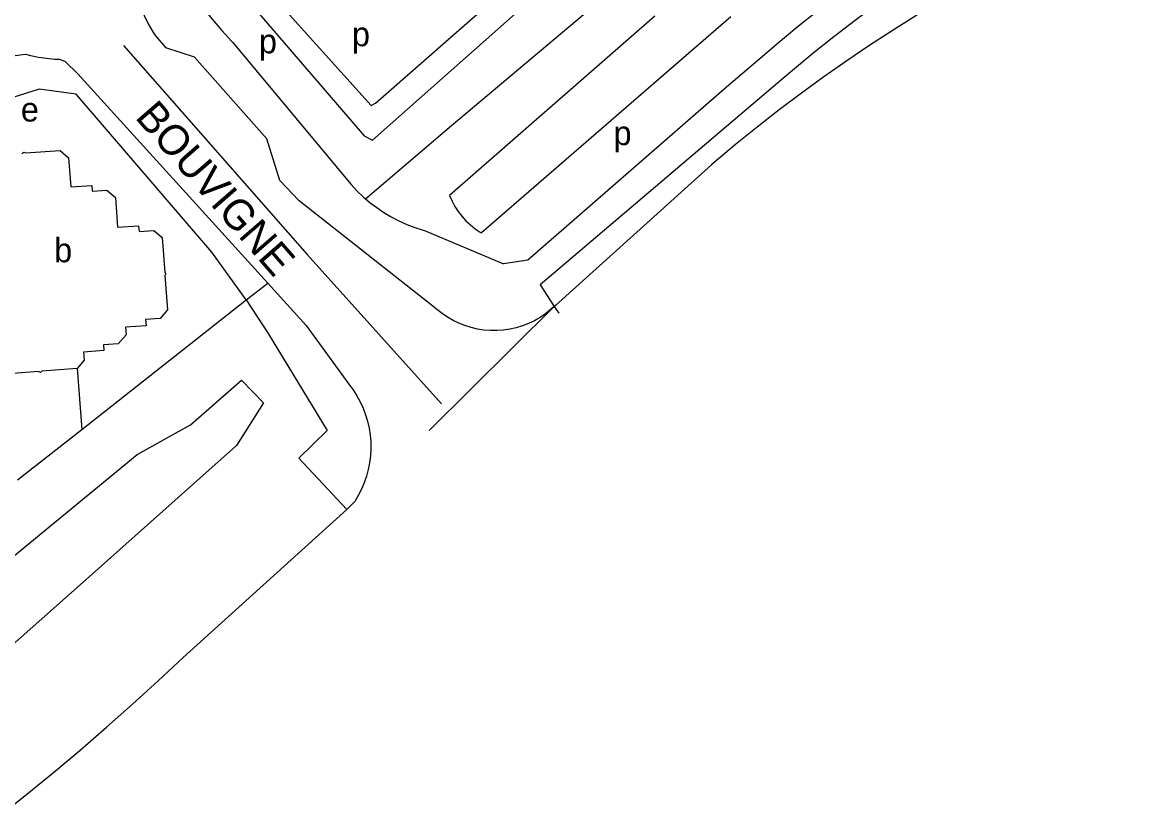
# Model space of a CAD drawing. Extents: x 157794 to 159375, y 380877 to 382306.
# Drawn here: x 158233.2 to 158416.4, y 380963.8 to 381095.2 of the extents above; entities that cross this region are included whole.
import ezdxf

# ---------------------------------------------------------------- set-up
doc = ezdxf.new("R2010")
doc.units = 0
for name, color, linetype in [('BLT_Basislijn', 7, 'Continuous'), ('BLT_Bebouwing', 7, 'Continuous'), ('BLT_Centroide', 7, 'Continuous'), ('BLT_Straatnaam', 7, 'Continuous'), ('BLT_Vlakafsluiter', 7, 'Continuous')]:
    doc.layers.add(name, color=color, linetype=linetype)

msp = doc.modelspace()

# ---------------------------------------------------------------- linework, layer by layer
at = {"layer": 'BLT_Basislijn'}
for p, q in [((158337.82, 381096.13), (158303.9, 381066.46)), ((158350.44, 381096.04), (158309.15, 381060.3)), ((158255.25, 381092.92), (158256.94, 381090.91)), ((158267.98, 381091.83), (158287.58, 381068.3)), ((158347.23, 381071.58), (158321.39, 381048.28)), ((158299.73, 381060.7), (158312.81, 381055.17)), ((158270.26, 381049.21), (158273.8, 381051.99)), ((158278.07, 381047.29), (158273.8, 381051.99)), ((158243.03, 381027.77), (158270.26, 381049.21)), ((158321.39, 381048.28), (158321.18, 381048.09)), ((158280.19, 381044.96), (158278.07, 381047.29)), ((158280.19, 381044.96), (158287.23, 381035.25)), ((158242.27, 381037.88), (158243.03, 381027.77)), ((158287.23, 381035.25), (158287.56, 381034.81)), ((158232.42, 381019.42), (158243.03, 381027.77)), ((158283.61, 381027.62), (158278.95, 381023.02)), ((158278.95, 381023.02), (158286.87, 381014.53)), ((158259.82, 380990.04), (158286.87, 381014.53)), ((158223.28, 380984.81), (158244.77, 381003.83))]:
    msp.add_line(p, q, dxfattribs=at)
for points in [[(158414.31, 381127.2), (158410.29, 381125.31), (158406.28, 381123.33), (158402.31, 381121.28), (158398.37, 381119.17), (158394.47, 381116.98), (158390.62, 381114.72), (158386.8, 381112.4), (158383.02, 381110), (158379.29, 381107.54), (158375.61, 381105.01), (158371.97, 381102.42), (158368.37, 381099.76), (158364.83, 381097.04), (158361.33, 381094.26), (158357.89, 381091.41), (158355.97, 381089.78)], [(158277.33, 381096.43), (158290.9, 381081.39), (158291.62, 381081.75), (158332.11, 381117.25), (158332.2, 381119.68), (158331.84, 381123.19), (158331.71, 381124.89)], [(158269.57, 381121.95), (158259.53, 381113.33), (158258.83, 381112.37), (158289.77, 381076.36), (158291.12, 381075.66), (158336.49, 381115.85)], [(158416.42, 381122.67), (158412.42, 381120.78), (158408.45, 381118.83), (158404.52, 381116.8), (158400.62, 381114.7), (158396.77, 381112.53), (158392.95, 381110.29), (158389.18, 381107.98), (158385.44, 381105.61), (158381.75, 381103.17), (158378.11, 381100.66), (158374.51, 381098.08), (158370.96, 381095.45), (158367.45, 381092.74), (158364, 381089.98), (158360.6, 381087.15), (158359.23, 381085.99)], [(158251.55, 381119.17), (158252.38, 381116.86), (158253.28, 381114.57), (158254.26, 381112.32), (158255.31, 381110.1), (158256.43, 381107.91), (158257.63, 381105.76), (158258.89, 381103.66), (158260.22, 381101.59), (158261.62, 381099.57), (158263.08, 381097.6), (158264.61, 381095.67), (158266.2, 381093.8), (158267.84, 381091.98), (158267.98, 381091.83)], [(158289.99, 381065.95), (158304.19, 381078.05), (158337.15, 381105.79)], [(158393.15, 381103.2), (158389.13, 381100.97), (158385.14, 381098.66), (158381.19, 381096.29), (158377.28, 381093.85), (158373.42, 381091.34), (158369.6, 381088.76), (158365.82, 381086.12), (158362.1, 381083.42), (158358.42, 381080.65), (158354.79, 381077.81), (158351.2, 381074.92), (158347.67, 381071.96), (158347.23, 381071.58)], [(158251.26, 381101.97), (158251.67, 381100.5), (158252.15, 381099.05), (158252.71, 381097.64), (158253.35, 381096.25), (158254.05, 381094.9), (158254.82, 381093.58), (158255.25, 381092.92)], [(158249.95, 381091.28), (158280.32, 381056.7), (158302.54, 381032)], [(158301.41, 381047.97), (158279.02, 381065.6), (158275.8, 381068.98), (158273.65, 381075.88), (158261.69, 381089.38), (158256.94, 381090.91)], [(158198.19, 381076.98), (158200.83, 381077.44), (158203.46, 381077.99), (158206.07, 381078.61), (158208.66, 381079.31), (158211.23, 381080.08), (158213.77, 381080.93), (158216.29, 381081.86), (158218.78, 381082.86), (158221.24, 381083.94), (158223.67, 381085.09), (158226.06, 381086.31), (158228.41, 381087.6), (158229.96, 381088.51), (158232, 381089.65), (158233.76, 381089.86)], [(158233.76, 381089.86), (158234.56, 381089.65), (158235.87, 381089.38), (158237.18, 381089.18), (158238.51, 381089.06), (158239.22, 381089.03)], [(158273.8, 381051.99), (158242.4, 381086.59), (158240.29, 381088.65), (158239.22, 381089.03)], [(158355.97, 381089.78), (158349.7, 381084.42), (158316.86, 381055.77), (158312.81, 381055.17)], [(158359.23, 381085.99), (158318.86, 381051.68), (158321.18, 381048.09)], [(158270.26, 381049.21), (158264.55, 381057.1), (158242.11, 381083.24), (158235.98, 381084.09), (158220.59, 381079.21)], [(158287.58, 381068.3), (158288.56, 381067.26), (158289.6, 381066.28), (158289.99, 381065.95)], [(158289.99, 381065.95), (158290.69, 381065.35), (158291.83, 381064.49), (158293.02, 381063.69), (158294.25, 381062.96), (158295.52, 381062.3), (158296.83, 381061.71), (158298.16, 381061.2), (158299.52, 381060.76), (158299.73, 381060.7)], [(158303.9, 381066.46), (158304.3, 381065.55), (158304.78, 381064.67), (158305.32, 381063.83), (158305.93, 381063.04), (158306.6, 381062.3), (158307.33, 381061.62), (158308.11, 381060.99), (158308.93, 381060.43), (158309.15, 381060.3)], [(158270.26, 381049.21), (158273.9, 381043.65), (158283.61, 381027.62)], [(158321.18, 381048.09), (158319.75, 381046.89), (158318.85, 381046.29), (158317.92, 381045.76), (158316.94, 381045.3), (158315.94, 381044.91), (158314.91, 381044.6), (158313.86, 381044.37), (158312.79, 381044.21), (158311.72, 381044.14), (158310.64, 381044.14), (158309.57, 381044.22), (158308.51, 381044.39), (158307.46, 381044.63), (158306.43, 381044.95), (158305.43, 381045.34), (158304.46, 381045.81), (158303.53, 381046.35), (158302.64, 381046.96), (158301.8, 381047.63), (158301.41, 381047.97)], [(158223.5, 381000), (158237.86, 381011.81), (158252.22, 381023.63), (158261.03, 381028.55), (158269.46, 381035.95), (158273.09, 381032.17), (158268.63, 381025.1), (158244.77, 381003.83)], [(158287.56, 381034.81), (158287.92, 381034.33), (158288.54, 381033.36), (158289.09, 381032.35), (158289.57, 381031.3), (158289.98, 381030.22), (158290.31, 381029.12), (158290.57, 381027.99), (158290.74, 381026.86), (158290.84, 381025.71), (158290.86, 381024.55), (158290.79, 381023.41), (158290.65, 381022.26), (158290.43, 381021.13), (158290.13, 381020.02), (158289.75, 381018.93), (158289.3, 381017.87), (158288.78, 381016.84), (158288.19, 381015.85), (158286.87, 381014.53)], [(158229.42, 380963.85), (158233.93, 380967.41), (158238.38, 380971.04), (158242.79, 380974.73), (158247.14, 380978.49), (158251.44, 380982.3), (158255.69, 380986.17), (158259.82, 380990.04)]]:
    msp.add_lwpolyline(points, dxfattribs=at)
at = {"layer": 'BLT_Bebouwing'}
for points in [[(158233.15, 381073.42), (158233.48, 381073.65), (158233.75, 381073.52), (158239.45, 381073.95), (158240.87, 381072.73), (158241.24, 381067.89), (158244.71, 381068.15), (158244.78, 381067.21), (158247.17, 381067.39), (158248.6, 381066.16), (158248.98, 381061.22), (158252.45, 381061.49), (158252.53, 381060.53), (158254.96, 381060.71), (158256.32, 381059.54), (158256.76, 381053.74), (158256.95, 381053.57), (158256.81, 381053.26), (158257.24, 381047.58), (158256.01, 381046.15), (158253.6, 381045.97), (158253.68, 381044.93), (158250.28, 381044.68), (158250.37, 381043.43), (158249.09, 381041.94), (158246.65, 381041.76), (158246.71, 381040.82), (158243.32, 381040.56), (158243.42, 381039.22), (158242.27, 381037.88)], [(158242.27, 381037.88), (158236.46, 381037.44), (158236.24, 381037.19), (158235.89, 381037.36), (158230.26, 381036.94), (158228.79, 381038.21), (158228.7, 381039.41), (158225.29, 381039.15), (158225.21, 381040.18), (158222.7, 381039.99), (158221.39, 381041.12)]]:
    msp.add_lwpolyline(points, dxfattribs=at)
at = {"layer": 'BLT_Vlakafsluiter'}
for q in [(158300.5, 381027.62), (158321.96, 381046.99)]:
    msp.add_line((158321.18, 381048.09), q, dxfattribs=at)

# ---------------------------------------------------------------- texts
at = {"layer": 'BLT_Centroide'}
for s, p in [('p', (158287.74, 381091.18)), ('p', (158272.35, 381090.01)), ('e', (158232.97, 381078.72)), ('p', (158331.01, 381074.81)), ('b', (158238.48, 381055.44))]:
    msp.add_text(s, height=4, dxfattribs=at).set_placement(p)
at = {"layer": 'BLT_Straatnaam'}
msp.add_text('BOUVIGNE', height=5, rotation=311.0649, dxfattribs=at).set_placement((158251.72, 381079.36))

doc.saveas('drawing.dxf')
